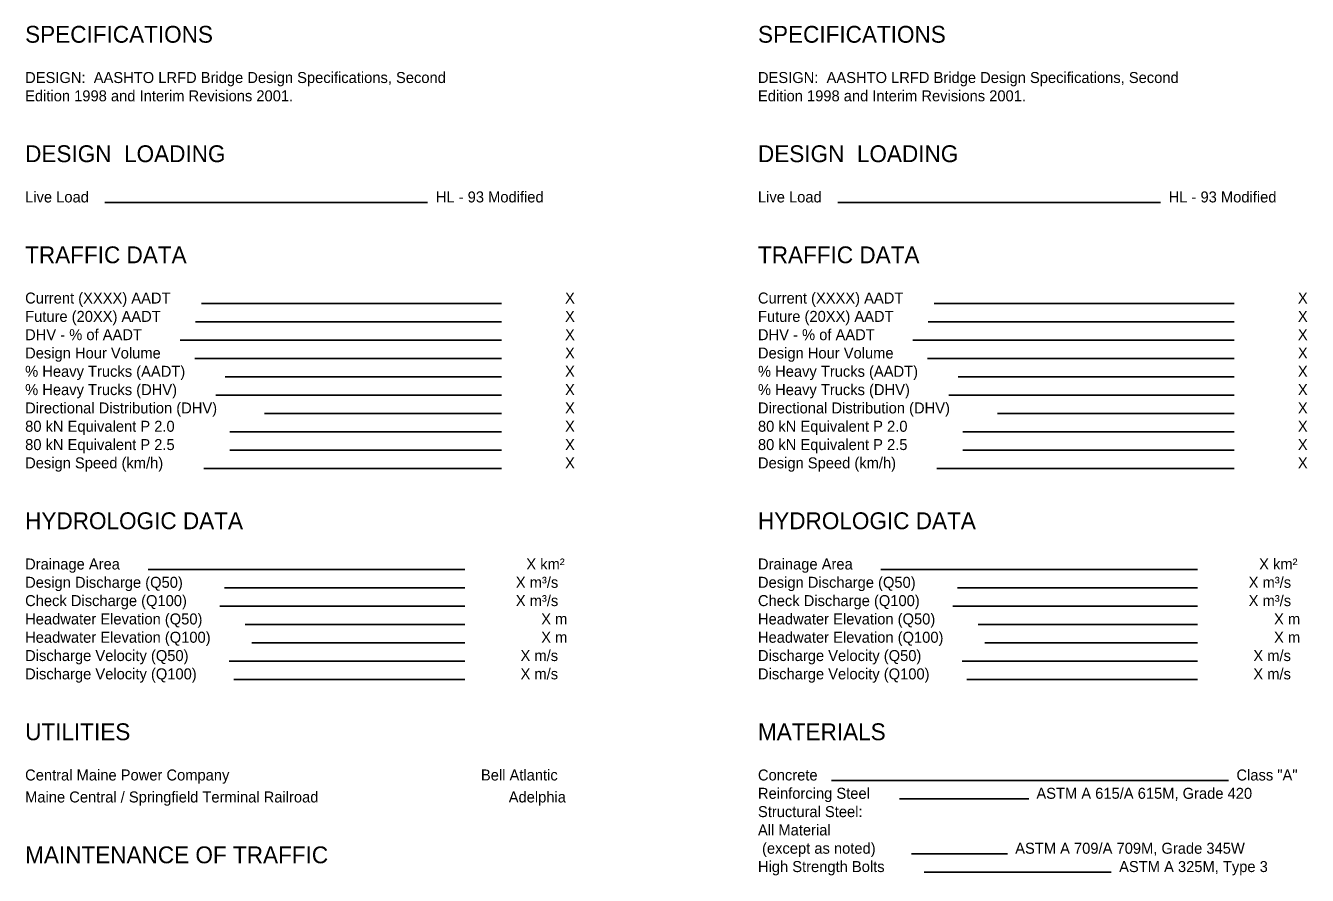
# Model space of a CAD drawing. Extents: x 604404 to 604584, y 419490 to 419604.
# Drawn here: x 604496.2 to 604583.7, y 419545.6 to 419603.6 of the extents above; entities that cross this region are included whole.
import ezdxf

# ---------------------------------------------------------------- set-up
doc = ezdxf.new("R2010")
doc.units = 0
doc.layers.add('Level 20', color=7, linetype='Continuous')

msp = doc.modelspace()

# ---------------------------------------------------------------- linework, layer by layer
at = {"layer": 'Level 20'}
for p, q in [((604501.653, 419591.524), (604523.675, 419591.524)), ((604551.653, 419591.524), (604573.675, 419591.524)), ((604508.237, 419584.624), (604528.714, 419584.624)), ((604558.237, 419584.624), (604578.714, 419584.624)), ((604507.828, 419583.374), (604528.714, 419583.374)), ((604557.828, 419583.374), (604578.714, 419583.374)), ((604506.784, 419582.124), (604528.714, 419582.124)), ((604556.784, 419582.124), (604578.714, 419582.124)), ((604507.782, 419580.874), (604528.714, 419580.874)), ((604557.782, 419580.874), (604578.714, 419580.874)), ((604509.871, 419579.624), (604528.714, 419579.624)), ((604559.871, 419579.624), (604578.714, 419579.624)), ((604509.235, 419578.374), (604528.714, 419578.374)), ((604559.235, 419578.374), (604578.714, 419578.374)), ((604512.55, 419577.124), (604528.714, 419577.124)), ((604562.55, 419577.124), (604578.714, 419577.124)), ((604510.189, 419575.874), (604528.714, 419575.874)), ((604560.189, 419575.874), (604578.714, 419575.874)), ((604510.189, 419574.624), (604528.714, 419574.624)), ((604560.189, 419574.624), (604578.714, 419574.624)), ((604508.418, 419573.374), (604528.714, 419573.374)), ((604558.418, 419573.374), (604578.714, 419573.374)), ((604504.604, 419566.474), (604526.214, 419566.474)), ((604554.604, 419566.474), (604576.214, 419566.474)), ((604509.826, 419565.224), (604526.214, 419565.224)), ((604559.826, 419565.224), (604576.214, 419565.224)), ((604509.508, 419563.974), (604526.214, 419563.974)), ((604559.508, 419563.974), (604576.214, 419563.974)), ((604511.233, 419562.724), (604526.214, 419562.724)), ((604561.233, 419562.724), (604576.214, 419562.724)), ((604511.687, 419561.474), (604526.214, 419561.474)), ((604561.687, 419561.474), (604576.214, 419561.474)), ((604510.144, 419560.224), (604526.214, 419560.224)), ((604560.144, 419560.224), (604576.214, 419560.224)), ((604510.461, 419558.974), (604526.214, 419558.974)), ((604560.461, 419558.974), (604576.214, 419558.974)), ((604551.226, 419552.074), (604578.323, 419552.074)), ((604555.862, 419550.824), (604564.688, 419550.824)), ((604556.687, 419547.074), (604563.246, 419547.074)), ((604557.545, 419545.824), (604570.321, 419545.824))]:
    msp.add_line(p, q, dxfattribs=at)

# ---------------------------------------------------------------- texts
for s, height, p in [('SPECIFICATIONS', 1.1499, (604496.214, 419602.424)), ('SPECIFICATIONS', 1.1499, (604546.214, 419602.424)), ('DESIGN:  AASHTO LRFD Bridge Design Specifications, Second', 0.75, (604496.214, 419599.674)), ('DESIGN:  AASHTO LRFD Bridge Design Specifications, Second', 0.75, (604546.214, 419599.674)), ('Edition 1998 and Interim Revisions 2001.', 0.75, (604496.214, 419598.424)), ('Edition 1998 and Interim Revisions 2001.', 0.75, (604546.214, 419598.424)), ('DESIGN  LOADING', 1.1499, (604496.214, 419594.274)), ('DESIGN  LOADING', 1.1499, (604546.214, 419594.274)), ('Live Load', 0.75, (604496.214, 419591.524)), ('HL - 93 Modified', 0.75, (604524.234, 419591.524)), ('Live Load', 0.75, (604546.214, 419591.524)), ('HL - 93 Modified', 0.75, (604574.234, 419591.524)), ('TRAFFIC DATA', 1.1499, (604496.214, 419587.374)), ('TRAFFIC DATA', 1.1499, (604546.214, 419587.374)), ('Current (XXXX) AADT', 0.75, (604496.214, 419584.624)), ('X', 0.75, (604533.052, 419584.624)), ('Current (XXXX) AADT', 0.75, (604546.214, 419584.624)), ('X', 0.75, (604583.052, 419584.624)), ('Future (20XX) AADT', 0.75, (604496.214, 419583.374)), ('X', 0.75, (604533.052, 419583.374)), ('Future (20XX) AADT', 0.75, (604546.214, 419583.374)), ('X', 0.75, (604583.052, 419583.374)), ('DHV - % of AADT', 0.75, (604496.214, 419582.124)), ('X', 0.75, (604533.052, 419582.124)), ('DHV - % of AADT', 0.75, (604546.214, 419582.124)), ('X', 0.75, (604583.052, 419582.124)), ('Design Hour Volume', 0.75, (604496.214, 419580.874)), ('X', 0.75, (604533.052, 419580.874)), ('Design Hour Volume', 0.75, (604546.214, 419580.874)), ('X', 0.75, (604583.052, 419580.874)), ('% Heavy Trucks (AADT)', 0.75, (604496.214, 419579.624)), ('X', 0.75, (604533.052, 419579.624)), ('% Heavy Trucks (AADT)', 0.75, (604546.214, 419579.624)), ('X', 0.75, (604583.052, 419579.624)), ('% Heavy Trucks (DHV)', 0.75, (604496.214, 419578.374)), ('X', 0.75, (604533.052, 419578.374)), ('% Heavy Trucks (DHV)', 0.75, (604546.214, 419578.374)), ('X', 0.75, (604583.052, 419578.374)), ('Directional Distribution (DHV)', 0.75, (604496.214, 419577.124)), ('X', 0.75, (604533.052, 419577.124)), ('Directional Distribution (DHV)', 0.75, (604546.214, 419577.124)), ('X', 0.75, (604583.052, 419577.124)), ('80 kN Equivalent P 2.0', 0.75, (604496.214, 419575.874)), ('X', 0.75, (604533.052, 419575.874)), ('80 kN Equivalent P 2.0', 0.75, (604546.214, 419575.874)), ('X', 0.75, (604583.052, 419575.874)), ('80 kN Equivalent P 2.5', 0.75, (604496.214, 419574.624)), ('X', 0.75, (604533.052, 419574.624)), ('80 kN Equivalent P 2.5', 0.75, (604546.214, 419574.624)), ('X', 0.75, (604583.052, 419574.624)), ('Design Speed (km/h)', 0.75, (604496.214, 419573.374)), ('X', 0.75, (604533.052, 419573.374)), ('Design Speed (km/h)', 0.75, (604546.214, 419573.374)), ('X', 0.75, (604583.052, 419573.374)), ('HYDROLOGIC DATA', 1.1499, (604496.214, 419569.224)), ('HYDROLOGIC DATA', 1.1499, (604546.214, 419569.224)), ('Drainage Area', 0.75, (604496.214, 419566.474)), ('X km²', 0.75, (604530.409, 419566.474)), ('Drainage Area', 0.75, (604546.214, 419566.474)), ('X km²', 0.75, (604580.409, 419566.474)), ('Design Discharge (Q50)', 0.75, (604496.214, 419565.224)), ('X m³/s', 0.75, (604529.693, 419565.224)), ('Design Discharge (Q50)', 0.75, (604546.214, 419565.224)), ('X m³/s', 0.75, (604579.693, 419565.224)), ('Check Discharge (Q100)', 0.75, (604496.214, 419563.974)), ('X m³/s', 0.75, (604529.693, 419563.974)), ('Check Discharge (Q100)', 0.75, (604546.214, 419563.974)), ('X m³/s', 0.75, (604579.693, 419563.974)), ('Headwater Elevation (Q50)', 0.75, (604496.214, 419562.724)), ('X m', 0.75, (604531.426, 419562.724)), ('Headwater Elevation (Q50)', 0.75, (604546.214, 419562.724)), ('X m', 0.75, (604581.426, 419562.724)), ('Headwater Elevation (Q100)', 0.75, (604496.214, 419561.474)), ('X m', 0.75, (604531.426, 419561.474)), ('Headwater Elevation (Q100)', 0.75, (604546.214, 419561.474)), ('X m', 0.75, (604581.426, 419561.474)), ('Discharge Velocity (Q50)', 0.75, (604496.214, 419560.224)), ('X m/s', 0.75, (604530.014, 419560.224)), ('Discharge Velocity (Q50)', 0.75, (604546.214, 419560.224)), ('X m/s', 0.75, (604580.014, 419560.224)), ('Discharge Velocity (Q100)', 0.75, (604496.214, 419558.974)), ('X m/s', 0.75, (604530.014, 419558.974)), ('Discharge Velocity (Q100)', 0.75, (604546.214, 419558.974)), ('X m/s', 0.75, (604580.014, 419558.974)), ('UTILITIES', 1.1499, (604496.214, 419554.824)), ('MATERIALS', 1.1499, (604546.214, 419554.824)), ('Central Maine Power Company', 0.75, (604496.214, 419552.074)), ('Bell Atlantic', 0.75, (604527.314, 419552.074)), ('Concrete', 0.75, (604546.214, 419552.074)), ('Class "A"', 0.75, (604578.863, 419552.074)), ('Maine Central / Springfield Terminal Railroad', 0.75, (604496.214, 419550.574)), ('Adelphia', 0.75, (604529.209, 419550.574)), ('Reinforcing Steel', 0.75, (604546.214, 419550.824)), ('ASTM A 615/A 615M, Grade 420', 0.75, (604565.212, 419550.824)), ('Structural Steel:', 0.75, (604546.214, 419549.574)), ('All Material', 0.75, (604546.214, 419548.324)), ('MAINTENANCE OF TRAFFIC', 1.1499, (604496.214, 419546.424)), (' (except as noted)', 0.75, (604546.214, 419547.074)), ('ASTM A 709/A 709M, Grade 345W', 0.75, (604563.766, 419547.074)), ('High Strength Bolts', 0.75, (604546.214, 419545.824)), ('ASTM A 325M, Type 3', 0.75, (604570.857, 419545.824))]:
    msp.add_text(s, height=height, dxfattribs=at).set_placement(p)

doc.saveas('drawing.dxf')
